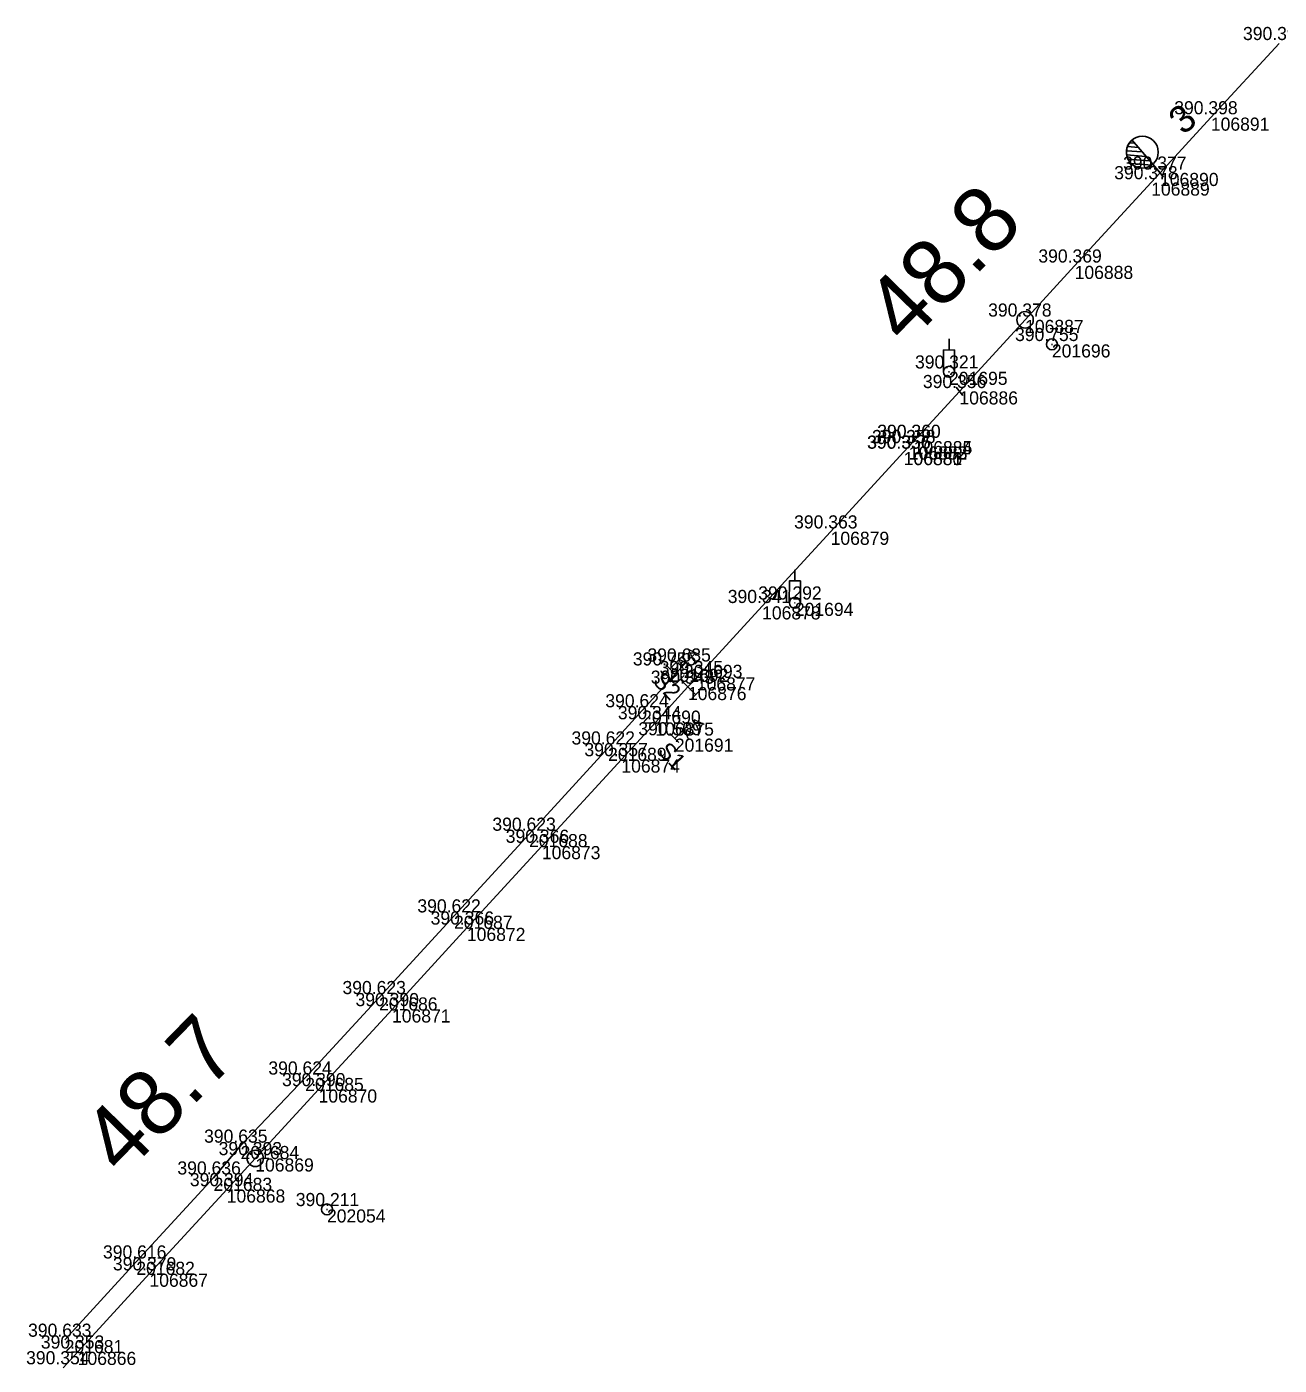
# Model space of a CAD drawing. Extents: x -545715 to -485912, y -1154994 to -1140055.
# Drawn here: x -507874 to -507759.4, y -1142415.4 to -1142293 of the extents above; entities that cross this region are included whole.
import ezdxf

# ---------------------------------------------------------------- set-up
doc = ezdxf.new("R2010")
doc.units = 0
for name, color, linetype in [('Vrstva 1', 7, 'Continuous'), ('Vrstva 14', 7, 'Continuous'), ('Vrstva 2', 7, 'Continuous'), ('Vrstva 3', 7, 'Continuous'), ('Vrstva 50', 7, 'Continuous'), ('Vrstva 6', 7, 'Continuous'), ('Vrstva 60', 7, 'Continuous'), ('Vrstva 61', 7, 'Continuous'), ('Vrstva 7', 7, 'Continuous')]:
    doc.layers.add(name, color=color, linetype=linetype)

msp = doc.modelspace()

# ---------------------------------------------------------------- linework, layer by layer
at = {"layer": 'Vrstva 1'}
for p, q in [((-507765.69, -1142301.26), (-507759.44, -1142294.47)), ((-507770.34, -1142306.31), (-507765.69, -1142301.26)), ((-507778.15, -1142314.82), (-507771.15, -1142307.2)), ((-507771.15, -1142307.2), (-507770.34, -1142306.31)), ((-507782.68, -1142319.76), (-507778.15, -1142314.82)), ((-507788.69, -1142326.3), (-507782.68, -1142319.76)), ((-507792.87, -1142330.85), (-507788.69, -1142326.3)), ((-507800.47, -1142339.14), (-507793.79, -1142331.85)), ((-507793.79, -1142331.85), (-507793.31, -1142331.33)), ((-507793.31, -1142331.33), (-507792.87, -1142330.85)), ((-507806.74, -1142345.96), (-507800.47, -1142339.14)), ((-507812.71, -1142352.46), (-507806.74, -1142345.96)), ((-507813.52, -1142353.34), (-507812.71, -1142352.46)), ((-507816.5, -1142356.59), (-507813.52, -1142353.34)), ((-507819.61, -1142359.97), (-507816.5, -1142356.59)), ((-507826.88, -1142367.89), (-507819.61, -1142359.97)), ((-507833.74, -1142375.37), (-507826.88, -1142367.89)), ((-507840.59, -1142382.83), (-507833.74, -1142375.37)), ((-507847.31, -1142390.15), (-507840.59, -1142382.83)), ((-507853.1, -1142396.46), (-507847.31, -1142390.15)), ((-507855.71, -1142399.3), (-507853.1, -1142396.46)), ((-507862.78, -1142407), (-507855.71, -1142399.3)), ((-507869.34, -1142414.15), (-507862.78, -1142407)), ((-507870.66, -1142415.6), (-507869.34, -1142414.15))]:
    msp.add_line(p, q, dxfattribs=at)
at = {"layer": 'Vrstva 14'}
for p, q in [((-507817.71, -1142355.5), (-507813.89, -1142351.31)), ((-507820.83, -1142358.9), (-507817.71, -1142355.5)), ((-507828.06, -1142366.79), (-507820.83, -1142358.9)), ((-507834.92, -1142374.26), (-507828.06, -1142366.79)), ((-507841.78, -1142381.73), (-507834.92, -1142374.26)), ((-507848.53, -1142389.09), (-507841.78, -1142381.73)), ((-507854.44, -1142395.32), (-507848.53, -1142389.09)), ((-507856.91, -1142398.23), (-507854.44, -1142395.32)), ((-507863.98, -1142405.91), (-507856.91, -1142398.23)), ((-507870.53, -1142413.06), (-507863.98, -1142405.91))]:
    msp.add_line(p, q, dxfattribs=at)
at = {"layer": 'Vrstva 2'}
for p, q in [((-507772.66, -1142303.6), (-507773.14, -1142303.56)), ((-507771, -1142305.53), (-507772.91, -1142303.31)), ((-507772.91, -1142303.31), (-507771.01, -1142305.53)), ((-507771.97, -1142304.4), (-507773.41, -1142304.29)), ((-507771.63, -1142304.81), (-507773.4, -1142304.67)), ((-507772.32, -1142304), (-507773.33, -1142303.92)), ((-507771.28, -1142305.21), (-507773.27, -1142305.06)), ((-507771.1, -1142305.6), (-507772.99, -1142305.45)), ((-507771.01, -1142305.53), (-507771, -1142305.53)), ((-507771, -1142305.53), (-507770.34, -1142306.31)), ((-507770.02, -1142306.71), (-507770.65, -1142305.92)), ((-507788.37, -1142326.69), (-507789, -1142325.91))]:
    msp.add_line(p, q, dxfattribs=at)
msp.add_circle((-507771.96, -1142304.42), 1.46, dxfattribs=at)
msp.add_arc((-507771.96, -1142304.42), 1.46, 130.6292, 310.5901, dxfattribs=at)
at = {"layer": 'Vrstva 3'}
for p, q in [((-507814.58, -1142352.99), (-507813.87, -1142352.28)), ((-507814.22, -1142352.63), (-507812.81, -1142354.05)), ((-507813.16, -1142354.4), (-507812.46, -1142353.69))]:
    msp.add_line(p, q, dxfattribs=at)
at = {"layer": 'Vrstva 50'}
for p, q in [((-507789.64, -1142321.51), (-507789.64, -1142322.51)), ((-507789.59, -1142324.51), (-507789.69, -1142324.51)), ((-507803.74, -1142342.64), (-507803.74, -1142343.64)), ((-507803.7, -1142345.64), (-507803.79, -1142345.64))]:
    msp.add_line(p, q, dxfattribs=at)
for points in [[(-507790.14, -1142324.51), (-507790.14, -1142322.51), (-507789.13, -1142322.52), (-507789.13, -1142324.51)], [(-507804.25, -1142345.64), (-507804.24, -1142343.64), (-507803.24, -1142343.64), (-507803.24, -1142345.64)]]:
    msp.add_lwpolyline(points, dxfattribs=at)
for centre in [(-507789.64, -1142324.51), (-507803.74, -1142345.64)]:
    msp.add_circle(centre, 0.506, dxfattribs=at)
at = {"layer": 'Vrstva 6'}
for p, q in [((-507813.78, -1142350.27), (-507815.18, -1142351.67)), ((-507815.54, -1142351.32), (-507814.83, -1142352.02)), ((-507815.07, -1142357.71), (-507814.37, -1142358.41)), ((-507813.32, -1142356.66), (-507814.72, -1142358.06))]:
    msp.add_line(p, q, dxfattribs=at)
at = {"layer": 'Vrstva 60'}
for p, q in [((-507765.69, -1142301.26), (-507765.69, -1142301.26)), ((-507771.15, -1142307.2), (-507771.15, -1142307.2)), ((-507770.34, -1142306.31), (-507770.34, -1142306.31)), ((-507778.15, -1142314.82), (-507778.15, -1142314.82)), ((-507782.68, -1142319.76), (-507782.68, -1142319.76)), ((-507780.23, -1142322), (-507780.23, -1142322)), ((-507789.64, -1142324.51), (-507789.64, -1142324.51)), ((-507788.69, -1142326.3), (-507788.69, -1142326.3)), ((-507793.79, -1142331.85), (-507793.79, -1142331.85)), ((-507793.78, -1142331.84), (-507793.78, -1142331.84)), ((-507793.32, -1142331.34), (-507793.32, -1142331.34)), ((-507793.31, -1142331.33), (-507793.31, -1142331.33)), ((-507792.87, -1142330.85), (-507792.87, -1142330.85)), ((-507792.87, -1142330.85), (-507792.87, -1142330.85)), ((-507800.47, -1142339.14), (-507800.47, -1142339.14)), ((-507806.74, -1142345.96), (-507806.74, -1142345.96)), ((-507803.74, -1142345.64), (-507803.74, -1142345.64)), ((-507813.89, -1142351.31), (-507813.89, -1142351.31)), ((-507815.18, -1142351.67), (-507815.18, -1142351.67)), ((-507812.71, -1142352.46), (-507812.71, -1142352.46)), ((-507813.52, -1142353.34), (-507813.52, -1142353.34)), ((-507817.71, -1142355.5), (-507817.71, -1142355.5)), ((-507816.5, -1142356.59), (-507816.5, -1142356.59)), ((-507820.83, -1142358.9), (-507820.83, -1142358.9)), ((-507814.72, -1142358.06), (-507814.72, -1142358.06)), ((-507819.61, -1142359.97), (-507819.61, -1142359.97)), ((-507828.06, -1142366.79), (-507828.06, -1142366.79)), ((-507826.88, -1142367.89), (-507826.88, -1142367.89)), ((-507834.92, -1142374.26), (-507834.92, -1142374.26)), ((-507833.74, -1142375.37), (-507833.74, -1142375.37)), ((-507841.78, -1142381.73), (-507841.78, -1142381.73)), ((-507840.59, -1142382.83), (-507840.59, -1142382.83)), ((-507848.53, -1142389.09), (-507848.53, -1142389.09)), ((-507847.31, -1142390.15), (-507847.31, -1142390.15)), ((-507854.44, -1142395.32), (-507854.44, -1142395.32)), ((-507853.1, -1142396.46), (-507853.1, -1142396.46)), ((-507856.91, -1142398.23), (-507856.91, -1142398.23)), ((-507855.71, -1142399.3), (-507855.71, -1142399.3)), ((-507846.54, -1142401.12), (-507846.54, -1142401.12)), ((-507863.98, -1142405.91), (-507863.98, -1142405.91)), ((-507862.78, -1142407), (-507862.78, -1142407)), ((-507870.53, -1142413.06), (-507870.53, -1142413.06)), ((-507869.34, -1142414.15), (-507869.34, -1142414.15))]:
    msp.add_line(p, q, dxfattribs=at)
at = {"layer": 'Vrstva 7'}
for p, q in [((-507780.28, -1142322), (-507780.18, -1142322)), ((-507846.59, -1142401.12), (-507846.49, -1142401.12))]:
    msp.add_line(p, q, dxfattribs=at)
for centre, radius in [((-507782.68, -1142319.76), 0.75), ((-507780.23, -1142322), 0.5), ((-507853.1, -1142396.46), 0.75), ((-507846.54, -1142401.12), 0.5)]:
    msp.add_circle(centre, radius, dxfattribs=at)

# ---------------------------------------------------------------- texts
at = {"layer": 'Vrstva 2'}
msp.add_text('3', height=2.5, rotation=40.5807, dxfattribs=at).set_placement((-507768.2, -1142302.92))
at = {"layer": 'Vrstva 6'}
for s, height, rotation, p in [('  A A ', 1, 45, (-507814.47, -1142352.38)), ('S2', 1.5, 313.4684, (-507816.82, -1142352.88)), ('  A A ', 1, 45, (-507814.01, -1142358.77)), ('S1', 1.5, 313.4684, (-507816.36, -1142359.27))]:
    msp.add_text(s, height=height, rotation=rotation, dxfattribs=at).set_placement(p)
at = {"layer": 'Vrstva 60'}
for s, p in [('106891', (-507765.69, -1142302.46)), ('106890', (-507770.34, -1142307.52)), ('106889', (-507771.15, -1142308.4)), ('106888', (-507778.15, -1142316.02)), ('106887', (-507782.68, -1142320.96)), ('201696', (-507780.23, -1142323.2)), ('201695', (-507789.64, -1142325.71)), ('106886', (-507788.69, -1142327.5)), ('106880', (-507793.79, -1142333.05)), ('106881', (-507793.78, -1142333.04)), ('106882', (-507793.32, -1142332.54)), ('106883', (-507793.31, -1142332.53)), ('106884', (-507792.87, -1142332.05)), ('106885', (-507792.87, -1142332.05)), ('106879', (-507800.47, -1142340.34)), ('106878', (-507806.74, -1142347.16)), ('201694', (-507803.74, -1142346.84)), ('201693', (-507813.89, -1142352.51)), ('201692', (-507815.18, -1142352.87)), ('106877', (-507812.71, -1142353.66)), ('106876', (-507813.52, -1142354.54)), ('201690', (-507817.71, -1142356.7)), ('106875', (-507816.5, -1142357.79)), ('201689', (-507820.83, -1142360.1)), ('201691', (-507814.72, -1142359.26)), ('106874', (-507819.61, -1142361.17)), ('201688', (-507828.06, -1142367.99)), ('106873', (-507826.88, -1142369.09)), ('201687', (-507834.92, -1142375.46)), ('106872', (-507833.74, -1142376.57)), ('201686', (-507841.78, -1142382.93)), ('106871', (-507840.59, -1142384.03)), ('201685', (-507848.53, -1142390.29)), ('106870', (-507847.31, -1142391.35)), ('201684', (-507854.44, -1142396.52)), ('106869', (-507853.1, -1142397.66)), ('201683', (-507856.91, -1142399.43)), ('106868', (-507855.71, -1142400.5)), ('202054', (-507846.54, -1142402.32)), ('201682', (-507863.98, -1142407.11)), ('106867', (-507862.78, -1142408.2)), ('201681', (-507870.53, -1142414.27)), ('106866', (-507869.34, -1142415.35))]:
    msp.add_text(s, height=1.2, dxfattribs=at).set_placement(p)
at = {"layer": 'Vrstva 61'}
for s, p in [('390.396', (-507762.75, -1142294.17)), ('390.398', (-507769.04, -1142300.96)), ('390.377', (-507773.72, -1142306.02)), ('390.378', (-507774.53, -1142306.9)), ('390.369', (-507781.47, -1142314.52)), ('390.378', (-507786.06, -1142319.46)), ('390.755', (-507783.6, -1142321.7)), ('390.321', (-507792.75, -1142324.21)), ('390.356', (-507792.03, -1142326)), ('390.360', (-507796.21, -1142330.55)), ('390.360', (-507796.2, -1142330.55)), ('390.356', (-507797.14, -1142331.55)), ('390.356', (-507797.12, -1142331.54)), ('390.358', (-507796.69, -1142331.04)), ('390.358', (-507796.68, -1142331.03)), ('390.363', (-507803.81, -1142338.84)), ('390.292', (-507807.09, -1142345.34)), ('390.341', (-507809.88, -1142345.66)), ('390.755', (-507818.56, -1142351.37)), ('390.635', (-507817.23, -1142351.01)), ('390.345', (-507816.11, -1142352.16)), ('390.343', (-507816.92, -1142353.04)), ('390.624', (-507821.08, -1142355.2)), ('390.344', (-507819.93, -1142356.29)), ('390.622', (-507824.17, -1142358.6)), ('390.509', (-507818.06, -1142357.76)), ('390.357', (-507822.99, -1142359.67)), ('390.623', (-507831.41, -1142366.49)), ('390.366', (-507830.19, -1142367.59)), ('390.622', (-507838.27, -1142373.96)), ('390.366', (-507837.06, -1142375.07)), ('390.623', (-507845.12, -1142381.43)), ('390.390', (-507843.93, -1142382.53)), ('390.624', (-507851.9, -1142388.79)), ('390.390', (-507850.65, -1142389.85)), ('390.635', (-507857.78, -1142395.02)), ('390.393', (-507856.45, -1142396.16)), ('390.636', (-507860.22, -1142397.93)), ('390.394', (-507859.08, -1142399)), ('390.211', (-507849.39, -1142400.82)), ('390.616', (-507867.03, -1142405.61)), ('390.379', (-507866.12, -1142406.7)), ('390.633', (-507873.88, -1142412.77)), ('390.353', (-507872.71, -1142413.85)), ('390.354', (-507874.06, -1142415.29))]:
    msp.add_text(s, height=1.2, dxfattribs=at).set_placement(p)
at = {"layer": 'Vrstva 7'}
for s, p in [('48.8', (-507793.56, -1142322.25)), ('48.7', (-507865.2, -1142398.23))]:
    msp.add_text(s, height=6, rotation=45.726, dxfattribs=at).set_placement(p)

doc.saveas('drawing.dxf')
